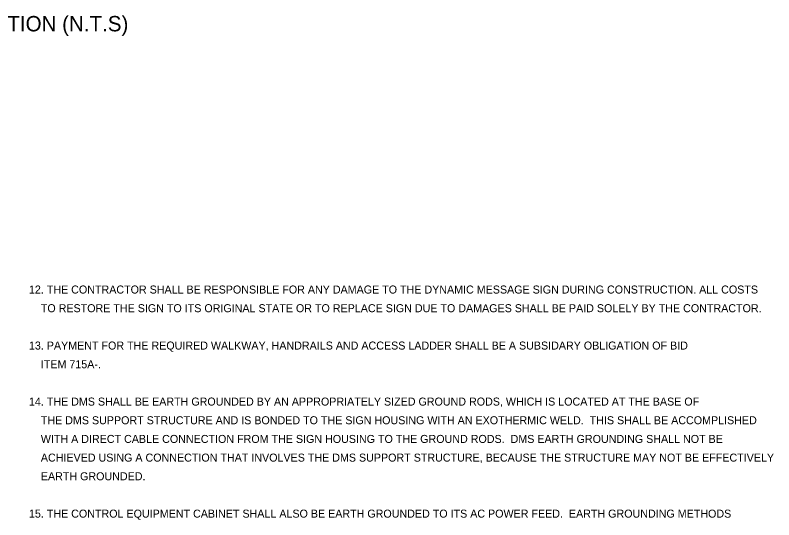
# Model space of a CAD drawing. Extents: x 515543 to 517243, y 661761 to 662861.
# Drawn here: x 516237.6 to 516647.1, y 662055.9 to 662328.3 of the extents above; entities that cross this region are included whole.
import ezdxf

# ---------------------------------------------------------------- set-up
doc = ezdxf.new("R2010")
doc.units = 0
doc.layers.add('Level 8', color=7, linetype='Continuous')
doc.layers.add('SHT-BNDRY', color=7, linetype='Continuous')

msp = doc.modelspace()

# ---------------------------------------------------------------- texts
at = {"layer": 'Level 8'}
msp.add_text('REQUIRED DMS BRIDGE STRUCTURE FRONT ELEVATION (N.T.S)', height=8.2944, rotation=360, dxfattribs=at).set_placement((515949.93, 662319.52))
at = {"layer": 'SHT-BNDRY'}
for s, p in [('12. THE CONTRACTOR SHALL BE RESPONSIBLE FOR ANY DAMAGE TO THE DYNAMIC MESSAGE SIGN DURING CONSTRUCTION. ALL COSTS ', (516245.07, 662178.01)), ('    TO RESTORE THE SIGN TO ITS ORIGINAL STATE OR TO REPLACE SIGN DUE TO DAMAGES SHALL BE PAID SOLELY BY THE CONTRACTOR.', (516245.07, 662167.93)), ('13. PAYMENT FOR THE REQUIRED WALKWAY, HANDRAILS AND ACCESS LADDER SHALL BE A SUBSIDARY OBLIGATION OF BID', (516245.07, 662147.77)), ('    ITEM 715A-.', (516245.07, 662137.69)), ('14. THE DMS SHALL BE EARTH GROUNDED BY AN APPROPRIATELY SIZED GROUND RODS, WHICH IS LOCATED AT THE BASE OF', (516245.07, 662117.53)), ('    THE DMS SUPPORT STRUCTURE AND IS BONDED TO THE SIGN HOUSING WITH AN EXOTHERMIC WELD.  THIS SHALL BE ACCOMPLISHED', (516245.07, 662107.45)), ('    WITH A DIRECT CABLE CONNECTION FROM THE SIGN HOUSING TO THE GROUND RODS.  DMS EARTH GROUNDING SHALL NOT BE', (516245.07, 662097.37)), ('    ACHIEVED USING A CONNECTION THAT INVOLVES THE DMS SUPPORT STRUCTURE, BECAUSE THE STRUCTURE MAY NOT BE EFFECTIVELY', (516245.07, 662087.29)), ('    EARTH GROUNDED.', (516245.07, 662077.21)), ('15. THE CONTROL EQUIPMENT CABINET SHALL ALSO BE EARTH GROUNDED TO ITS AC POWER FEED.  EARTH GROUNDING METHODS', (516245.07, 662057.05))]:
    msp.add_text(s, height=4.32, dxfattribs=at).set_placement(p)

doc.saveas('drawing.dxf')
